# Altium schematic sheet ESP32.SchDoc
size A3; SheetNumber: 3; SheetTotal: 16
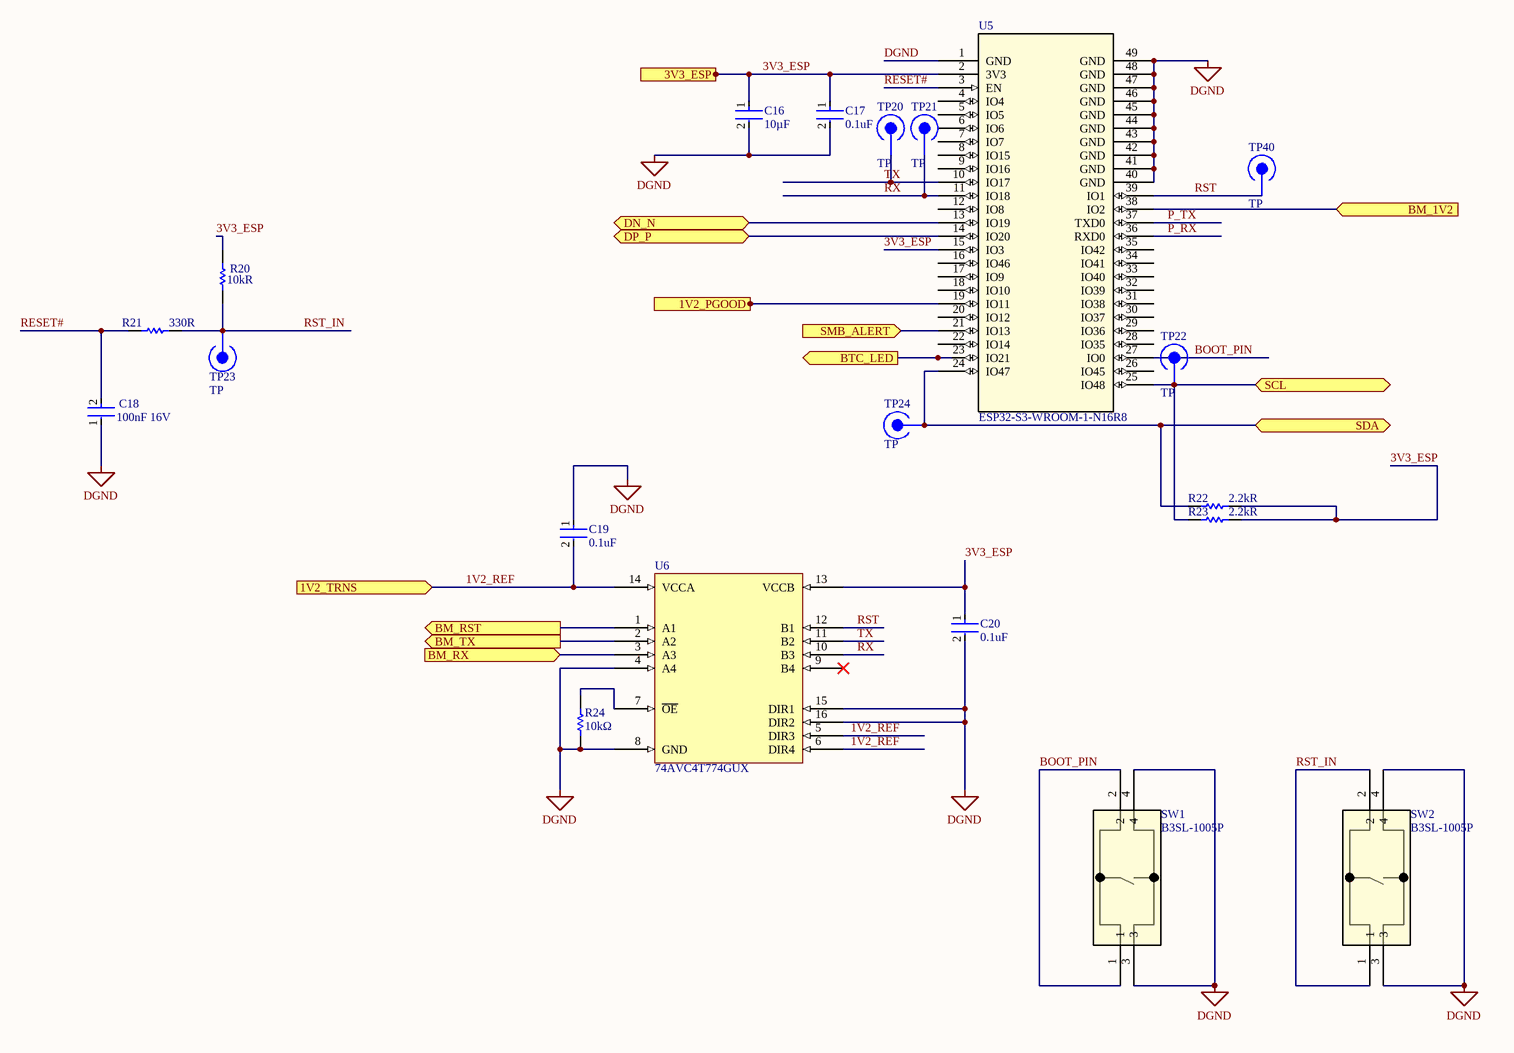
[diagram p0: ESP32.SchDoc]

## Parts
C16  value 10µF  [FP-GRM21B-0_15-MFG]  (hidden comment: GRM21BR61E106KA73L)
C17  value 0.1uF  [FP-CC0402-IPC_C]  (hidden comment: CC0402KRX7R7BB104)
C18  value 100nF  Rating: 16V  [FP-GRM15-MFG]  (hidden comment: GRM155R71C104KA88D)
C19  value 0.1uF  [FP-CC0402-IPC_C]  (hidden comment: CC0402KRX7R7BB104)
C20  value 0.1uF  [FP-CC0402-IPC_C]  (hidden comment: CC0402KRX7R7BB104)
R20  value 10kR  [RESC1005X40X25LL10T10]  (hidden comment: RK73H1ETTP1002F)
R21  value 330R  [RESC1005X40X25ML10T10]  (hidden comment: RK73H1ETTP3300F)
R22  value 2.2kR  [RESC1005X40X25NL10T10]  (hidden comment: RK73H1ETTP2201F)
R23  value 2.2kR  [RESC1005X40X25NL10T10]  (hidden comment: RK73H1ETTP2201F)
R24  value 10kΩ  [RESC1005X40X25LL10T10]  (hidden comment: RK73B1ETTP103J)
SW1  B3SL-1005P  [SW_B3SL-1002P_OMR]
SW2  B3SL-1005P  [SW_B3SL-1002P_OMR]
TP20  TP  [TP-Footprint-1]
TP21  TP  [TP-Footprint-1]
TP22  TP  [TP-Footprint-1]
TP23  TP  [TP-Footprint-1]
TP24  TP  [TP-Footprint-1]
TP40  TP  [TP-Footprint-1]
U5  ESP32-S3-WROOM-1-N16R8  [ESP32-S3-WROOM-1-N16R8-Footprint-1]
U6  74AVC4T774GUX  [74AVC4T774GUX-Footprint-1]

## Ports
1V2_PGOOD (in), 1V2_TRNS (in), 3V3_ESP (in), BM_1V2 (in), BM_RST (out), BM_RX (in), BM_TX (out), BTC_LED (out), DN_N (bidir), DP_P (bidir), SCL (bidir), SDA (bidir), SMB_ALERT (in)

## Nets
DGND: C16.2 C17.2 C18.1 C19.1 C20.2 R24.2 SW1.3 SW1.4 SW2.3 SW2.4 U5.1(GND) U5.40(GND) U5.41(GND) U5.42(GND) U5.43(GND) U5.44(GND) U5.45(GND) U5.46(GND) U5.47(GND) U5.48(GND) U5.49(GND) U6.4(A4) U6.8(GND) U6.15(DIR1) U6.16(DIR2)
1V2_PGOOD: U5.19(IO11) ; port 1V2_PGOOD
1V2_REF: C19.2 U6.5(DIR3) U6.6(DIR4) U6.14(VCCA) ; port 1V2_TRNS
3V3_ESP: C16.1 C17.1 C20.1 R20.2 R22.2 R23.2 U5.2(3V3) U5.15(IO3) U6.13(VCCB) ; port 3V3_ESP
BM_1V2: U5.38(IO2) ; port BM_1V2
BM_RST: U6.1(A1) ; port BM_RST
BM_RX: U6.3(A3) ; port BM_RX
BM_TX: U6.2(A2) ; port BM_TX
BOOT_PIN: SW1.1 SW1.2 U5.27(IO0)
BTC_LED: U5.23(IO21) ; port BTC_LED
DN_N: U5.13(IO19) ; port DN_N
DP_P: U5.14(IO20) ; port DP_P
P_RX: U5.36(RXD0)
P_TX: U5.37(TXD0)
RESET#: C18.2 R21.1 U5.3(EN)
RST: TP40.1 U5.39(IO1) U6.12(B1)
RST_IN: R20.1 R21.2 SW2.1 SW2.2 TP23.1
RX: TP21.1 U5.11(IO18) U6.10(B3)
SCL: R23.1 TP22.1 U5.25(IO48) ; port SCL
SDA: R22.1 TP24.1 U5.24(IO47) ; port SDA
SMB_ALERT: U5.21(IO13) ; port SMB_ALERT
TX: TP20.1 U5.10(IO17) U6.11(B2)
NetR24_1: R24.1 U6.7(~{OE})

Not connected (* = marked no-connect by the designer): U5 4(IO4) 5(IO5) 6(IO6) 7(IO7) 8(IO15) 9(IO16) 12(IO8) 16(IO46) 17(IO9) 18(IO10) 20(IO12) 22(IO14) 26(IO45) 28(IO35) 29(IO36) 30(IO37) 31(IO38) 32(IO39) 33(IO40) 34(IO41) 35(IO42); U6 9(B4)*

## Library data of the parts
C16 = CMP-001-00145-3: Ceramic Capacitor, Multilayer, Ceramic, 25V, 10% +Tol, 10% -Tol, X5R, 15% TC, 10uF, Surface Mount, 0805; Manufacturer: Murata; Reel Size: 8mm; Vendor: TTI; Template: MR_0805
C17 C19 C20 = CMP-001-00094-1: Multilayer Ceramic Capacitor, 0.1 uF, 25 V, ± 10%, X7R, 0402 [1005 Metric]; Rating: 16V; Reel Size: 8mm; Vendor: TTI
C18 = CMP-001-00203-2: Ceramic Capacitor, Multilayer, Ceramic, 16V, 10% +Tol, 10% -Tol, X7R, 15% TC, 0.1uF, Surface Mount, 0402; Manufacturer: Murata; Reel Size: 8mm; Vendor: TTI; Template: MR_0402
R20 = CMP-x00150-1: Fixed Resistor, Metal Glaze/thick Film, 0.1W, 10000ohm, 75V, 1% +/-Tol, 100ppm/Cel, Surface Mount, 0402
R21 = CMP-2002-04371-1: Manufacturer: KOA Speer
R22 R23 = CMP-2002-03812-1: Manufacturer: KOA Speer
R24 = CMP-009-00227-1: Fixed Resistor, Metal Glaze/thick Film, 0.1W, 10000ohm, 75V, 5% +/-Tol, 200ppm/Cel, Surface Mount, 0402; Rating: 1/10W; Vendor: TTI
SW1 SW2 = CMP-011-00029-1: No Description Available; Mfr_Name: Omron
TP20-TP24 TP40 = CMP-001-0086-3: digital shovel test point
U5 = CMP-226-000000-01-A-2: No Description Available; Mfr_Name: Espressif Systems
U6 = CMP-x00133-2: 74AVC4T774 - 4-bit dual supply translating transceiver; 3-state; Manufacturer: Nexperia; Template: NX_XQFN_16; Reel Width: 8mm; Vendor: TTI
